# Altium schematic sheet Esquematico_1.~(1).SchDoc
size A4
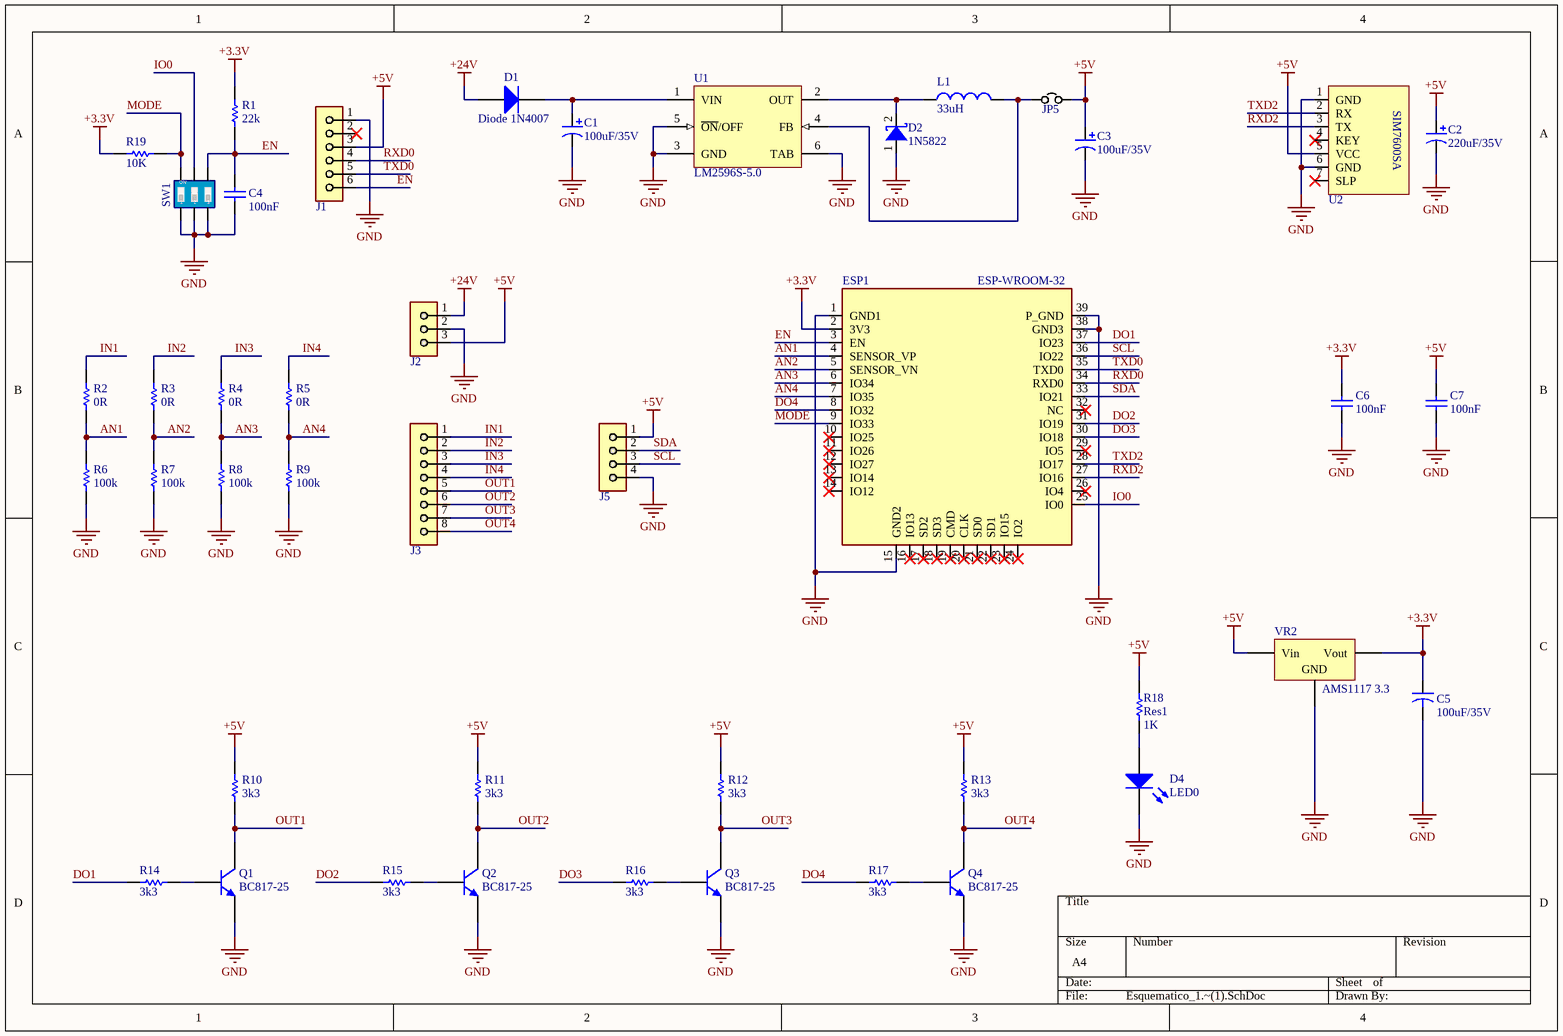
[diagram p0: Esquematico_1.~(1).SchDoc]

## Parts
C1  value 100uF/35V  [CAP_ELEC_1]  (hidden comment: CAP_ELEC)
C2  value 220uF/35V  [CAP_ELEC_3.5MM]  (hidden comment: CAP_ELEC)
C3  value 100uF/35V  [CAP_ELEC_1]  (hidden comment: CAP_ELEC)
C4  value 100nF  [CAP]  (hidden comment: Cap)
C5  value 100uF/35V  [CAP_ELEC_1]  (hidden comment: Cap2)
C6  value 100nF  [6-0805_M]  (hidden comment: Cap)
C7  value 100nF  [6-0805_M]  (hidden comment: Cap)
D1  Diode 1N4007  [DO214]
D2  1N5822  [DO214]
D4  LED0  [6-0805_M]
ESP1  ESP-WROOM-32  [ESP32-WROOM-32D]
J1  SIL_6  [SIL_6]  (value not drawn)
J2  SIL_3  [SIL_3]  (value not drawn)
J3  SIL_8  [SIL_8]  (value not drawn)
J5  SIL_4  [SIL_4]  (value not drawn)
JP5  JUMPER  [SIL_2]  (value not drawn)
L1  value 33uH  [INDUTOR_SMD]  (hidden comment: Inductor)
Q1  BC817-25  [SOT-23A_M]
Q2  BC817-25  [SOT-23A_M]
Q3  BC817-25  [SOT-23A_M]
Q4  BC817-25  [SOT-23A_M]
R1  value 22k  [6-0805_M]  (hidden comment: Res1)
R2  value 0R  [6-0805_M]  (hidden comment: Res1)
R3  value 0R  [6-0805_M]  (hidden comment: Res1)
R4  value 0R  [6-0805_M]  (hidden comment: Res1)
R5  value 0R  [6-0805_M]  (hidden comment: Res1)
R6  value 100k  [6-0805_M]  (hidden comment: Res1)
R7  value 100k  [6-0805_M]  (hidden comment: Res1)
R8  value 100k  [6-0805_M]  (hidden comment: Res1)
R9  value 100k  [6-0805_M]  (hidden comment: Res1)
R10  value 3k3  [6-0805_M]  (hidden comment: Res1)
R11  value 3k3  [6-0805_M]  (hidden comment: Res1)
R12  value 3k3  [6-0805_M]  (hidden comment: Res1)
R13  value 3k3  [6-0805_M]  (hidden comment: Res1)
R14  value 3k3  [6-0805_M]  (hidden comment: Res1)
R15  value 3k3  [6-0805_M]  (hidden comment: Res1)
R16  value 3k3  [6-0805_M]  (hidden comment: Res1)
R17  value 3k3  [6-0805_M]  (hidden comment: Res1)
R18  Res1  value 1K  [6-0805_M]
R19  value 10K  [6-0805_M]  (hidden comment: Res1)
SW1  DIP_SWITCH_3  [DIP_6]  (value not drawn)
U1  LM2596S-5.0  [TS5B_M]
U2  SIM7600  [Modulo_SIM7600SA]  (value not drawn)
VR2  AMS1117 3.3  [SOT-223B_M]

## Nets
+3.3V: C5.1 C6.2 ESP1.2(3V3) R1.2 R19.2 VR2.3(Vout)
+5V: C2.1 C3.1 C7.2 J1.3 J2.3 J5.1 JP5.2 R10.1 R11.1 R12.1 R13.1 R18.1 U2.5(VCC) VR2.1(Vin)
+24V: D1.1(A) J2.1
GND: C1.2 C2.2 C3.2 C4.1 C5.2 C6.1 C7.1 D2.1 D4.2(K) ESP1.1(GND1) ESP1.15(GND2) ESP1.38(GND3) ESP1.39(P_GND) J1.1 J2.2 J5.4 Q1.2(E) Q2.2(E) Q3.2(E) Q4.2(E) R6.1 R7.1 R8.1 R9.1 SW1.1 SW1.2 SW1.3 U1.3(GND) U1.5(~{ON}/OFF) U1.6(TAB) U2.1(GND) U2.6(GND) VR2.2(GND)
AN1: ESP1.4(SENSOR_VP) R2.1 R6.2
AN2: ESP1.5(SENSOR_VN) R3.1 R7.2
AN3: ESP1.6(IO34) R4.1 R8.2
AN4: ESP1.7(IO35) R5.1 R9.2
DO1: ESP1.37(IO23) R14.2
DO2: ESP1.31(IO19) R15.2
DO3: ESP1.30(IO18) R16.2
DO4: ESP1.8(IO32) R17.2
EN: C4.2 ESP1.3(EN) J1.6 R1.1 SW1.4
IN1: J3.1 R2.2
IN2: J3.2 R3.2
IN3: J3.3 R4.2
IN4: J3.4 R5.2
IO0: ESP1.25(IO0) SW1.5
MODE: ESP1.9(IO33) R19.1 SW1.6
OUT1: J3.5 Q1.3(C) R10.2
OUT2: J3.6 Q2.3(C) R11.2
OUT3: J3.7 Q3.3(C) R12.2
OUT4: J3.8 Q4.3(C) R13.2
RXD0: ESP1.34(RXD0) J1.4
RXD2: ESP1.27(IO16) U2.3(TX)
SCL: ESP1.36(IO22) J5.3
SDA: ESP1.33(IO21) J5.2
TXD0: ESP1.35(TXD0) J1.5
TXD2: ESP1.28(IO17) U2.2(RX)
NetC1_1: C1.1 D1.2(K) U1.1(VIN)
NetD2_2: D2.2 L1.1 U1.2(OUT)
NetD4_1: D4.1(A) R18.2
NetJP5_1: JP5.1 L1.2 U1.4(FB)
NetQ1_1: Q1.1(B) R14.1
NetQ2_1: Q2.1(B) R15.1
NetQ3_1: Q3.1(B) R16.1
NetQ4_1: Q4.1(B) R17.1

Not connected (* = marked no-connect by the designer): ESP1 10(IO25)* 11(IO26)* 12(IO27)* 13(IO14)* 14(IO12)* 16(IO13)* 17(SD2)* 18(SD3)* 19(CMD)* 20(CLK)* 21(SD0)* 22(SD1)* 23(IO15)* 24(IO2)* 26(IO4)* 29(IO5)* 32(NC)*; J1 2*; U2 4(KEY)* 7(SLP)*

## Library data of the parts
C1-C3 = CAP_ELEC: Capacitor eletrolitico radial
C4 C6 C7 = Cap: Capacitor
C5 = Cap2: Capacitor
D1 = Diode 1N4007: 1 Amp General Purpose Rectifier
D4 = LED0: Typical INFRARED GaAs LED
J3 = SIL_8: SIL 8 Connector
L1 = Inductor: Code_IEC: 1005
Q1-Q4 = BC817-25: NPN General Purpose Amplifier
R1-R19 = Res1: Resistor
SW1 = DIP_SWITCH_3: DIP SWITCH 3 WAYS
U1 = LM2596S-5.0: SIMPLE SWITCHER® Power Converter 150 KHz 3A Step-Down Voltage Regulator, 5-pin TO-263; Manufacturer: National Semiconductor; PackageTopMarking: NSUZXYTTE#*LM2596S*-5.0 P+; PowerWise: N
U2 = Modulo_SIM7600
VR2 = Volt Reg: Voltage Regulator; pin to pad: 1>3 2>1 3>2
